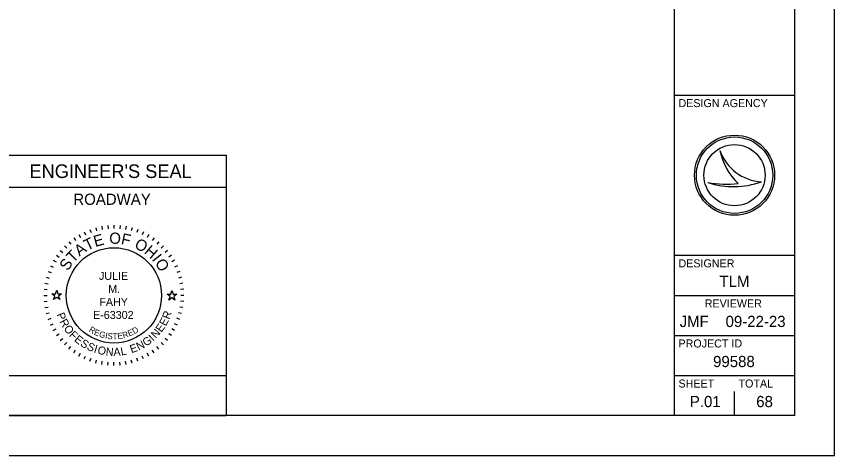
# Model space of a CAD drawing. Extents: x -12 to 34, y 0 to 22.
# Drawn here: x 23.78 to 34, y 0 to 5.48 of the extents above; entities that cross this region are included whole.
import ezdxf

# ---------------------------------------------------------------- set-up
doc = ezdxf.new("R2010")
doc.units = 0
for name, color, linetype in [('GM_X_County', 7, 'Continuous'), ('GM_X_Section', 7, 'Continuous'), ('GM_X_Township', 7, 'Continuous')]:
    doc.layers.add(name, color=color, linetype=linetype)

msp = doc.modelspace()

# ---------------------------------------------------------------- linework, layer by layer
at = {"layer": 'GM_X_County'}
for p, q in [((32, 0.5), (32, 21.5)), ((32, 4.5), (33.5, 4.5)), ((32, 2.5), (33.5, 2.5)), ((32, 2), (33.5, 2)), ((32, 1.5), (33.5, 1.5)), ((32, 1), (33.5, 1))]:
    msp.add_line(p, q, dxfattribs=at)
msp.add_lwpolyline([(1.5, 21.5), (33.5, 21.5), (33.5, 0.5), (1.5, 0.5)], close=True, dxfattribs=at)
at = {"layer": 'GM_X_Section'}
msp.add_lwpolyline([(0, 0), (34, 0), (34, 22), (0, 22)], close=True, dxfattribs=at)
at = {"layer": 'GM_X_Township'}
for p, q in [((32.567, 3.81), (32.567, 3.81)), ((23.6, 3.75), (26.4, 3.75)), ((26.4, 3.75), (26.4, 0.5)), ((32.75, 3.5), (32.75, 3.5)), ((32.417, 3.41), (32.417, 3.41)), ((33.087, 3.419), (33.087, 3.419)), ((23.6, 3.35), (26.4, 3.35)), ((24.848, 2.862), (24.855, 2.822)), ((24.924, 2.872), (24.927, 2.832)), ((25, 2.875), (25, 2.835)), ((25.076, 2.872), (25.073, 2.832)), ((25.152, 2.862), (25.145, 2.822)), ((24.63, 2.793), (24.647, 2.757)), ((24.701, 2.822), (24.714, 2.785)), ((24.774, 2.845), (24.784, 2.807)), ((25.226, 2.845), (25.216, 2.807)), ((25.299, 2.822), (25.286, 2.785)), ((25.37, 2.793), (25.353, 2.757)), ((24.438, 2.67), (24.463, 2.64)), ((24.498, 2.717), (24.521, 2.684)), ((24.563, 2.758), (24.583, 2.723)), ((25.437, 2.758), (25.417, 2.723)), ((25.502, 2.717), (25.479, 2.684)), ((25.562, 2.67), (25.537, 2.64)), ((24.33, 2.562), (24.36, 2.537)), ((24.381, 2.619), (24.41, 2.59)), ((25.619, 2.619), (25.59, 2.59)), ((25.67, 2.562), (25.64, 2.537)), ((24.283, 2.502), (24.316, 2.479)), ((25.717, 2.502), (25.684, 2.479)), ((24.207, 2.37), (24.243, 2.353)), ((24.242, 2.438), (24.277, 2.418)), ((25.758, 2.438), (25.723, 2.418)), ((25.793, 2.37), (25.757, 2.353)), ((24.178, 2.299), (24.215, 2.286)), ((25.822, 2.299), (25.785, 2.286)), ((24.138, 2.152), (24.178, 2.145)), ((24.155, 2.226), (24.193, 2.216)), ((25.845, 2.226), (25.807, 2.216)), ((25.862, 2.152), (25.822, 2.145)), ((24.128, 2.076), (24.168, 2.073)), ((25.872, 2.076), (25.832, 2.073)), ((24.125, 2), (24.165, 2)), ((25.875, 2), (25.835, 2)), ((24.128, 1.924), (24.168, 1.927)), ((24.138, 1.848), (24.178, 1.855)), ((25.862, 1.848), (25.822, 1.855)), ((25.872, 1.924), (25.832, 1.927)), ((24.155, 1.774), (24.193, 1.784)), ((25.845, 1.774), (25.807, 1.784)), ((24.178, 1.701), (24.215, 1.714)), ((24.207, 1.63), (24.243, 1.647)), ((25.793, 1.63), (25.757, 1.647)), ((25.822, 1.701), (25.785, 1.714)), ((24.242, 1.563), (24.277, 1.583)), ((25.758, 1.563), (25.723, 1.583)), ((24.283, 1.498), (24.316, 1.521)), ((24.33, 1.438), (24.36, 1.463)), ((25.67, 1.438), (25.64, 1.463)), ((25.717, 1.498), (25.684, 1.521)), ((24.381, 1.381), (24.41, 1.41)), ((24.438, 1.33), (24.463, 1.36)), ((25.562, 1.33), (25.537, 1.36)), ((25.619, 1.381), (25.59, 1.41)), ((24.498, 1.283), (24.521, 1.316)), ((24.563, 1.242), (24.583, 1.277)), ((24.63, 1.207), (24.647, 1.243)), ((25.37, 1.207), (25.353, 1.243)), ((25.437, 1.242), (25.417, 1.277)), ((25.502, 1.283), (25.479, 1.316)), ((24.701, 1.178), (24.714, 1.215)), ((24.774, 1.155), (24.784, 1.193)), ((24.848, 1.138), (24.855, 1.178)), ((24.924, 1.128), (24.927, 1.168)), ((25, 1.125), (25, 1.165)), ((25.076, 1.128), (25.073, 1.168)), ((25.152, 1.138), (25.145, 1.178)), ((25.226, 1.155), (25.216, 1.193)), ((25.299, 1.178), (25.286, 1.215)), ((32.75, 0.5), (32.75, 0.8)), ((32.375, 0.675), (32.375, 0.675)), ((23.6, 0.5), (26.4, 0.5))]:
    msp.add_line(p, q, dxfattribs=at)
for points in [[(24.224, 2.02), (24.271, 2.02), (24.285, 2.065), (24.299, 2.02), (24.346, 2.02), (24.308, 1.992), (24.323, 1.948), (24.285, 1.975), (24.247, 1.948), (24.262, 1.992)], [(25.663, 2.015), (25.71, 2.015), (25.724, 2.059), (25.739, 2.015), (25.785, 2.015), (25.748, 1.987), (25.762, 1.942), (25.724, 1.97), (25.686, 1.942), (25.701, 1.987)], [(23.6, 0.5), (23.6, 1), (26.4, 1), (26.4, 0.5)]]:
    msp.add_lwpolyline(points, close=True, dxfattribs=at)
for centre, radius in [((32.75, 3.5), 0.5), ((32.75, 3.5), 0.477), ((32.75, 3.5), 0.477), ((32.75, 3.5), 0.382), ((25, 2), 0.595)]:
    msp.add_circle(centre, radius, dxfattribs=at)
for centre, radius, start, end in [((33.116, 3.998), 0.58, 198.9257, 198.9319), ((33.347, 3.97), 0.796, 191.6379, 191.6421), ((33.116, 3.998), 0.58, 198.9319, 267.1657), ((33.347, 3.97), 0.796, 191.6421, 226.0947), ((32.739, 4.37), 1.013, 251.4576, 290.0832), ((32.648, 4.654), 1.266, 259.4964, 259.4995), ((32.739, 4.37), 1.013, 251.4527, 251.4576), ((32.648, 4.654), 1.266, 259.4995, 276.6672)]:
    msp.add_arc(centre, radius, start, end, dxfattribs=at)

# ---------------------------------------------------------------- texts
for s, height, p in [('DESIGN AGENCY', 0.1, (32.05, 4.35)), ("ENGINEER'S SEAL", 0.17, (23.945, 3.465)), ('ROADWAY', 0.14, (24.493, 3.13)), ('DESIGNER', 0.1, (32.05, 2.35)), ('JULIE', 0.1, (24.813, 2.194)), ('TLM', 0.14, (32.562, 2.105)), ('M.', 0.1, (24.929, 2.031)), ('FAHY', 0.1, (24.818, 1.869)), ('REVIEWER', 0.1, (32.378, 1.85)), ('E-63302', 0.1, (24.74, 1.706)), ('JMF', 0.14, (32.064, 1.605)), ('09-22-23', 0.14, (32.638, 1.605)), ('PROJECT ID', 0.1, (32.05, 1.35)), ('99588', 0.14, (32.482, 1.105)), ('SHEET', 0.1, (32.05, 0.85)), ('TOTAL', 0.1, (32.8, 0.85)), ('P.01', 0.14, (32.192, 0.605)), ('68', 0.14, (33.021, 0.605))]:
    msp.add_text(s, height=height, dxfattribs=at).set_placement(p)
for s, height, rotation, p in [('E', 0.14, 15.7571, (24.767, 2.603)), ('O', 0.14, 359.7812, (24.942, 2.644)), ('F', 0.14, 347.4362, (25.081, 2.642)), ('T', 0.14, 25.7167, (24.666, 2.554)), ('O', 0.14, 332.2586, (25.246, 2.598)), ('T', 0.14, 46.4344, (24.492, 2.4)), ('A', 0.14, 36.4747, (24.569, 2.482)), ('H', 0.14, 319.9136, (25.368, 2.532)), ('S', 0.14, 57.1924, (24.426, 2.298)), ('I', 0.14, 308.367, (25.467, 2.447)), ('O', 0.14, 303.1491, (25.506, 2.403)), ('P', 0.1, 291.494, (24.282, 1.762)), ('R', 0.1, 69.2322, (25.691, 1.694)), ('R', 0.1, 298.7311, (24.318, 1.673)), ('E', 0.1, 54.758, (25.593, 1.531)), ('E', 0.1, 61.9951, (25.647, 1.609)), ('O', 0.1, 306.4666, (24.368, 1.585)), ('F', 0.1, 314.7068, (24.434, 1.498)), ('R', 0.075, 327.8239, (24.68, 1.554)), ('E', 0.075, 337.7777, (24.744, 1.513)), ('G', 0.075, 344.2727, (24.808, 1.485)), ('I', 0.075, 350.6464, (24.887, 1.463)), ('E', 0.075, 8.9826, (25.049, 1.453)), ('R', 0.075, 17.6836, (25.119, 1.463)), ('E', 0.075, 23.3052, (25.191, 1.486)), ('D', 0.075, 31.466, (25.255, 1.514)), ('N', 0.1, 47.0224, (25.524, 1.455)), ('E', 0.1, 321.4393, (24.497, 1.435)), ('S', 0.1, 328.6764, (24.572, 1.377)), ('S', 0.075, 353.7858, (24.915, 1.458)), ('T', 0.075, 3.0061, (24.985, 1.451)), ('N', 0.1, 27.3113, (25.31, 1.31)), ('G', 0.1, 35.0469, (25.4, 1.358)), ('I', 0.1, 43.287, (25.488, 1.422)), ('S', 0.1, 335.9134, (24.654, 1.328)), ('I', 0.1, 343.1505, (24.742, 1.289)), ('O', 0.1, 346.8859, (24.788, 1.274)), ('N', 0.1, 355.1261, (24.895, 1.251)), ('A', 0.1, 2.8617, (24.996, 1.244)), ('L', 0.1, 10.0987, (25.092, 1.249)), ('E', 0.1, 20.0742, (25.22, 1.277))]:
    msp.add_text(s, height=height, rotation=rotation, dxfattribs=at).set_placement(p)

doc.saveas('drawing.dxf')
